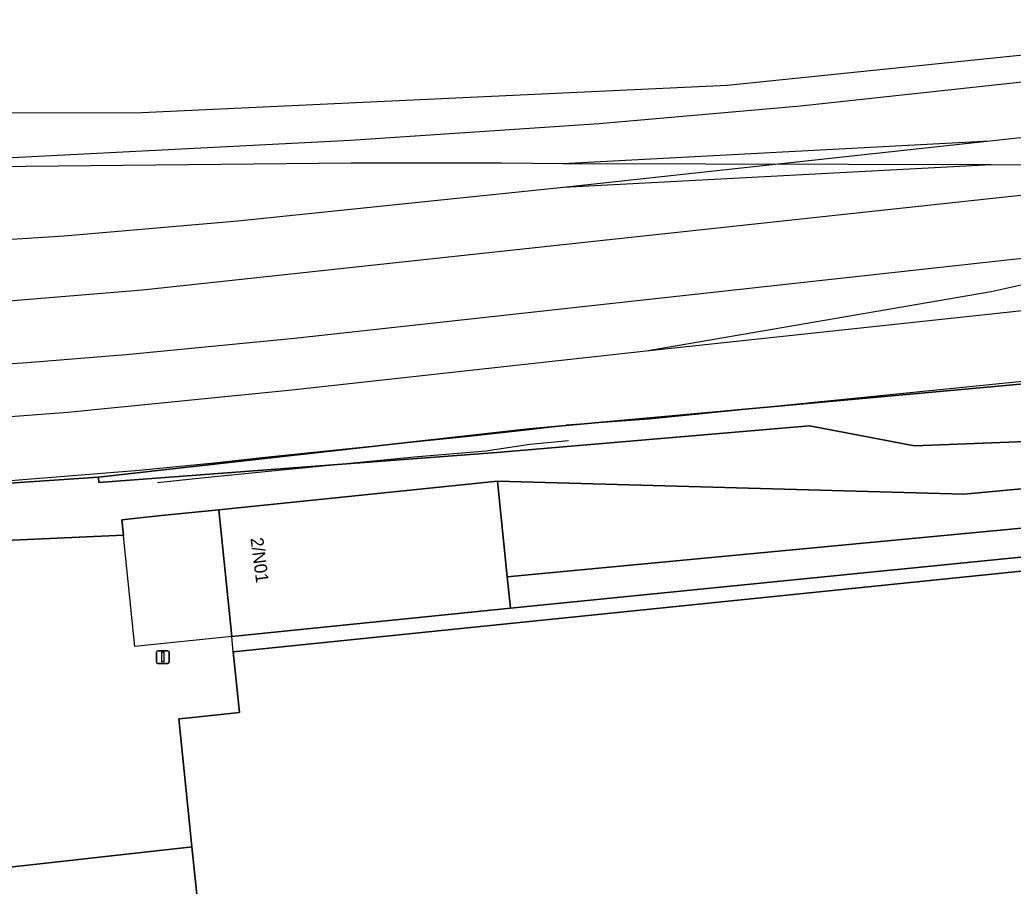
# Model space of a CAD drawing. Extents: x 160675 to 161153, y 383241 to 383714.
# Drawn here: x 160986.7 to 161064.7, y 383635.2 to 383703.2 of the extents above; entities that cross this region are included whole.
import ezdxf

# ---------------------------------------------------------------- set-up
doc = ezdxf.new("R2010")
doc.units = 0
for name, color, linetype in [('IMGEO_Erf', 7, 'Continuous'), ('IMGEO_Geluidsscherm', 7, 'Continuous'), ('IMGEO_Groenvoorziening', 7, 'Continuous'), ('IMGEO_Hek', 7, 'Continuous'), ('IMGEO_Lichtmast', 7, 'Continuous'), ('IMGEO_Pand', 7, 'Continuous'), ('IMGEO_Pand_nummerreeks', 7, 'Continuous'), ('IMGEO_Spoor', 7, 'Continuous'), ('IMGEO_Spoorbaan_halfverhard', 7, 'Continuous'), ('IMGEO_Struiken', 7, 'Continuous'), ('IMGEO_Voetpad_open', 7, 'Continuous')]:
    doc.layers.add(name, color=color, linetype=linetype)

msp = doc.modelspace()

# ---------------------------------------------------------------- linework, layer by layer
at = {"layer": 'IMGEO_Erf'}
msp.add_lwpolyline([(160984.439, 383636.549), (161000, 383638.275), (161000.191, 383638.296), (161000, 383640.144), (160999.151, 383648.35), (161000, 383648.437), (161003.926, 383648.838), (161003.438, 383653.613), (161085.53, 383662.01), (161085.439, 383663.057), (161025.202, 383657.046), (161003.316, 383654.807), (161002.299, 383664.755), (160997.79, 383664.294), (160994.689, 383663.977), (160994.814, 383662.758), (160951.872, 383660.829)], dxfattribs=at)
at = {"layer": 'IMGEO_Geluidsscherm'}
msp.add_lwpolyline([(160945.514, 383665.197), (160949.168, 383665.136), (160956.874, 383665.407), (160969.924, 383665.923), (160976.501, 383666.352), (160982.995, 383666.806), (160996.034, 383667.853), (161001.931, 383668.436), (161005.941, 383668.886), (161015.57, 383669.879), (161021.966, 383670.542), (161026.455, 383671.017), (161029.599, 383671.397)], dxfattribs=at)
at = {"layer": 'IMGEO_Groenvoorziening'}
msp.add_lwpolyline([(161024.953, 383659.484), (161085.252, 383665.198), (161085.226, 383665.497), (161084.914, 383669.077), (161073.219, 383667.119), (161060.798, 383665.989), (161024.185, 383666.994)], close=True, dxfattribs=at)
at = {"layer": 'IMGEO_Hek'}
for points in [[(161084.075, 383676.703), (161036.085, 383671.875), (161029.577, 383671.395)], [(160997.495, 383666.904), (161000.946, 383667.256), (161006.193, 383667.777), (161017.636, 383668.92), (161023.273, 383669.372), (161026.737, 383669.895), (161029.77, 383670.184)], [(160997.79, 383664.294), (160994.689, 383663.977), (160994.814, 383662.758)], [(160903.94, 383660.754), (160939.748, 383660.285), (160994.814, 383662.758)], [(160994.873, 383662.183), (160994.814, 383662.758)], [(161003.316, 383654.807), (160995.707, 383654.029), (160994.873, 383662.183)], [(161003.438, 383653.613), (161003.316, 383654.807)]]:
    msp.add_lwpolyline(points, dxfattribs=at)
at = {"layer": 'IMGEO_Lichtmast'}
for p, q in [((160997.399, 383652.794), (160997.399, 383653.594)), ((160997.399, 383653.594), (160997.399, 383652.794)), ((160997.499, 383653.694), (160998.289, 383653.694)), ((160998.289, 383653.694), (160997.499, 383653.694)), ((160998.389, 383653.594), (160998.389, 383652.794)), ((160998.389, 383652.794), (160998.389, 383653.594)), ((160998.289, 383652.694), (160997.499, 383652.694)), ((160997.499, 383652.694), (160998.289, 383652.694))]:
    msp.add_line(p, q, dxfattribs=at)
msp.add_lwpolyline([(160997.819, 383653.569), (160997.969, 383653.569), (160997.969, 383652.819), (160997.819, 383652.819), (160997.819, 383653.569)], dxfattribs=at)
for centre, start, end in [((160997.499, 383653.594), 90, 180), ((160997.499, 383653.594), 90, 180), ((160998.289, 383653.594), 0, 90), ((160998.289, 383653.594), 360, 90), ((160997.499, 383652.794), 180, 270), ((160997.499, 383652.794), 180, 270), ((160998.289, 383652.794), 270, 0), ((160998.289, 383652.794), 270, 0)]:
    msp.add_arc(centre, 0.1, start, end, dxfattribs=at)
at = {"layer": 'IMGEO_Pand'}
msp.add_lwpolyline([(161025.202, 383657.046), (161024.953, 383659.484), (161024.185, 383666.994), (161002.299, 383664.755), (161003.316, 383654.807)], close=True, dxfattribs=at)
msp.add_lwpolyline([(161085.53, 383662.01), (161003.438, 383653.613), (161003.926, 383648.838), (161000, 383648.437), (160999.151, 383648.35), (161000, 383640.144), (161000.191, 383638.296), (161000.887, 383631.567), (161001.177, 383628.766), (161001.334, 383627.253), (161001.934, 383621.456), (161002.067, 383620.168), (161002.684, 383614.206), (161003.697, 383604.41), (161004.319, 383598.403), (161005.816, 383583.932), (161007.41, 383584.1), (161007.86, 383579.72), (161009.37, 383579.88), (161018.91, 383580.89), (161018.41, 383585.64), (161027.23, 383586.54), (161027.74, 383581.8), (161076.456, 383586.789)], dxfattribs=at)
at = {"layer": 'IMGEO_Spoor'}
for points in [[(161012.649, 383693.758), (161032.175, 383695.071), (161047.981, 383696.456), (161093.204, 383701.345)], [(160811.517, 383698.315), (160814.059, 383697.799), (160825.832, 383695.612), (160842.277, 383692.934), (160858.011, 383690.688), (160869.475, 383689.255), (160881.135, 383688.009), (160893.397, 383686.893), (160910.142, 383685.73), (160923.179, 383685.098), (160935.664, 383684.814), (160948.776, 383684.705), (160960.823, 383684.871), (160971.128, 383685.196), (160978.592, 383685.522), (160990.162, 383686.261), (161003.797, 383687.434), (161029.372, 383690.072)], [(161062.845, 383693.706), (161094.765, 383697.147)], [(160969.213, 383691.528), (161012.649, 383693.758)], [(161029.304, 383691.933), (161062.845, 383693.706)], [(161029.372, 383690.072), (161062.845, 383693.706)], [(160807.257, 383693.046), (160814.167, 383691.641), (160825.478, 383689.569), (160842.512, 383686.724), (160853.887, 383684.978), (160865.29, 383683.494), (160871.006, 383682.891), (160876.734, 383682.401), (160911.142, 383679.852), (160920.849, 383679.492), (160931.37, 383679.275), (160941.893, 383679.249), (160951.606, 383679.382), (160960.506, 383679.646), (160971.018, 383680.123), (160980.713, 383680.732), (160996.307, 383682.013), (161070.12, 383689.969)], [(160969.213, 383691.528), (161012.704, 383691.973)], [(161012.704, 383691.973), (161024.509, 383691.995), (161029.304, 383691.933)], [(161029.304, 383691.933), (161062.943, 383691.847)], [(161029.372, 383690.072), (161062.943, 383691.847)], [(161062.943, 383691.847), (161070.021, 383691.829)], [(160804.225, 383689.295), (160806.659, 383688.787), (160818.376, 383686.573), (160835.996, 383683.564), (160847.763, 383681.765), (160859.552, 383680.145), (160871.367, 383678.714), (160883.21, 383677.482), (160895.075, 383676.427), (160906.949, 383675.599), (160912.894, 383675.33), (160930.74, 383674.73), (160938.54, 383674.633), (160946.99, 383674.64), (160954.79, 383674.753), (160962.587, 383674.968), (160971.03, 383675.313), (160978.819, 383675.739), (160987.25, 383676.315), (160995.024, 383676.948), (161008.233, 383678.23), (161066.129, 383684.581)], [(161063.228, 383680.168), (161099.605, 383684.129)], [(160799.541, 383683.502), (160802.19, 383682.941), (160820.969, 383679.396), (160839.844, 383676.405), (160858.798, 383673.97), (160877.817, 383672.093), (160894.974, 383670.883), (160912.157, 383670.145), (160915.977, 383670.021), (160933.175, 383669.811), (160952.283, 383670.118), (160971.374, 383670.985), (160990.431, 383672.414), (161008.04, 383674.179), (161035.872, 383677.224)], [(161062.945, 383681.887), (161066.49, 383682.676)], [(161035.872, 383677.224), (161062.945, 383681.887)], [(161035.872, 383677.224), (161063.228, 383680.168)]]:
    msp.add_lwpolyline(points, dxfattribs=at)
at = {"layer": 'IMGEO_Spoorbaan_halfverhard'}
msp.add_lwpolyline([(160971.538, 383665.887), (160992.861, 383667.306), (161026.677, 383671.109), (161088.25, 383676.706), (161093.127, 383679.163), (161101.13, 383680.028), (161100.944, 383680.528), (161092.512, 383703.206), (161042.213, 383698.051), (160996.257, 383695.919), (160922.821, 383695.85)], dxfattribs=at)
at = {"layer": 'IMGEO_Struiken'}
msp.add_lwpolyline([(160951.872, 383660.829), (160994.814, 383662.758), (160994.689, 383663.977), (160997.79, 383664.294), (161002.299, 383664.755), (161024.185, 383666.994), (161060.798, 383665.989), (161073.219, 383667.119), (161084.914, 383669.077), (161088.518, 383669.68), (161097.199, 383674.315), (161100.414, 383678.137), (161101.13, 383680.028), (161093.127, 383679.163), (161088.25, 383676.706), (161080.923, 383672.358), (161074.948, 383671.225), (161065.671, 383670.113), (161056.928, 383669.786), (161048.686, 383671.351), (161024.145, 383669.262), (160992.877, 383666.895), (160992.861, 383667.306), (160971.538, 383665.887)], dxfattribs=at)
msp.add_lwpolyline([(160992.877, 383666.895), (161024.145, 383669.262), (161048.686, 383671.351), (161056.928, 383669.786), (161065.671, 383670.113), (161074.948, 383671.225), (161080.923, 383672.358), (161088.25, 383676.706), (161026.677, 383671.109), (160992.861, 383667.306)], close=True, dxfattribs=at)
at = {"layer": 'IMGEO_Voetpad_open'}
for points in [[(161025.202, 383657.046), (161085.439, 383663.057), (161085.252, 383665.198), (161024.953, 383659.484)], [(161000, 383631.486), (161000.887, 383631.567), (161000.191, 383638.296), (161000, 383638.275), (160984.439, 383636.549), (160984.882, 383630.105)]]:
    msp.add_lwpolyline(points, close=True, dxfattribs=at)

# ---------------------------------------------------------------- texts
at = {"layer": 'IMGEO_Pand_nummerreeks'}
msp.add_text('2/N01', height=1, rotation=277.35238, dxfattribs=at).set_placement((161004.784, 383662.514))

doc.saveas('drawing.dxf')
